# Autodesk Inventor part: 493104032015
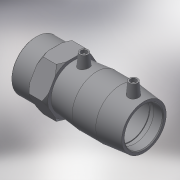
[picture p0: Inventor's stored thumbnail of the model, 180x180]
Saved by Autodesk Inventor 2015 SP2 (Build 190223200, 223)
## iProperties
Created: 2017-06
Part Number: 493104032015
Material: Generic
Description: PLASSON FEMALE TRANSITION COUPLER 32 x 1.1/4"
Document SubType Name: Modeling
Designer: KIM
Mass: 95.8914 g
Surface Area: 353.492 cm^2
Volume: 95.8914 cm^3
Density: 1 g/cm^3
Appearance: Default
Author: KIM
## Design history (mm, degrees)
derived "493104.ipt"
feature "Solid1::493104.ipt"
tag "TaggingFeature1"
body "Solid1"
other parameters: "d0" = 99, "d1" = 32, "d2" = 44, "d3" = 39, "d4" = 33, "d5" = 39.6, "d6" = 30.4, "d7" = 32, "d8" = 168 deg, "d10" = 15.6, "d11" = 5.2, "d29" = 52, "d30" = 14, "d31" = 34.65, "d34" = 5 deg, "d41" = 4, "d42" = 14, "d43" = 0, "d48" = 3, "d49" = 0, "d55" = 25, "d57" = 28, "d59" = 38.952, "d60" = 22.5, "d70" = 44, "d71" = 12.5, "d72" = 0, "d73" = 45 deg, "d74" = 2.8, "d75" = 45 deg, "d77" = 0.48, "d80" = 0.64, "d_" = 32, "L_" = 124, "L_1" = 39, "D_1" = 44, "A_" = 52, "d_2" = 12, "L_2" = 25, "D_" = 28, "R_p" = 38.952
